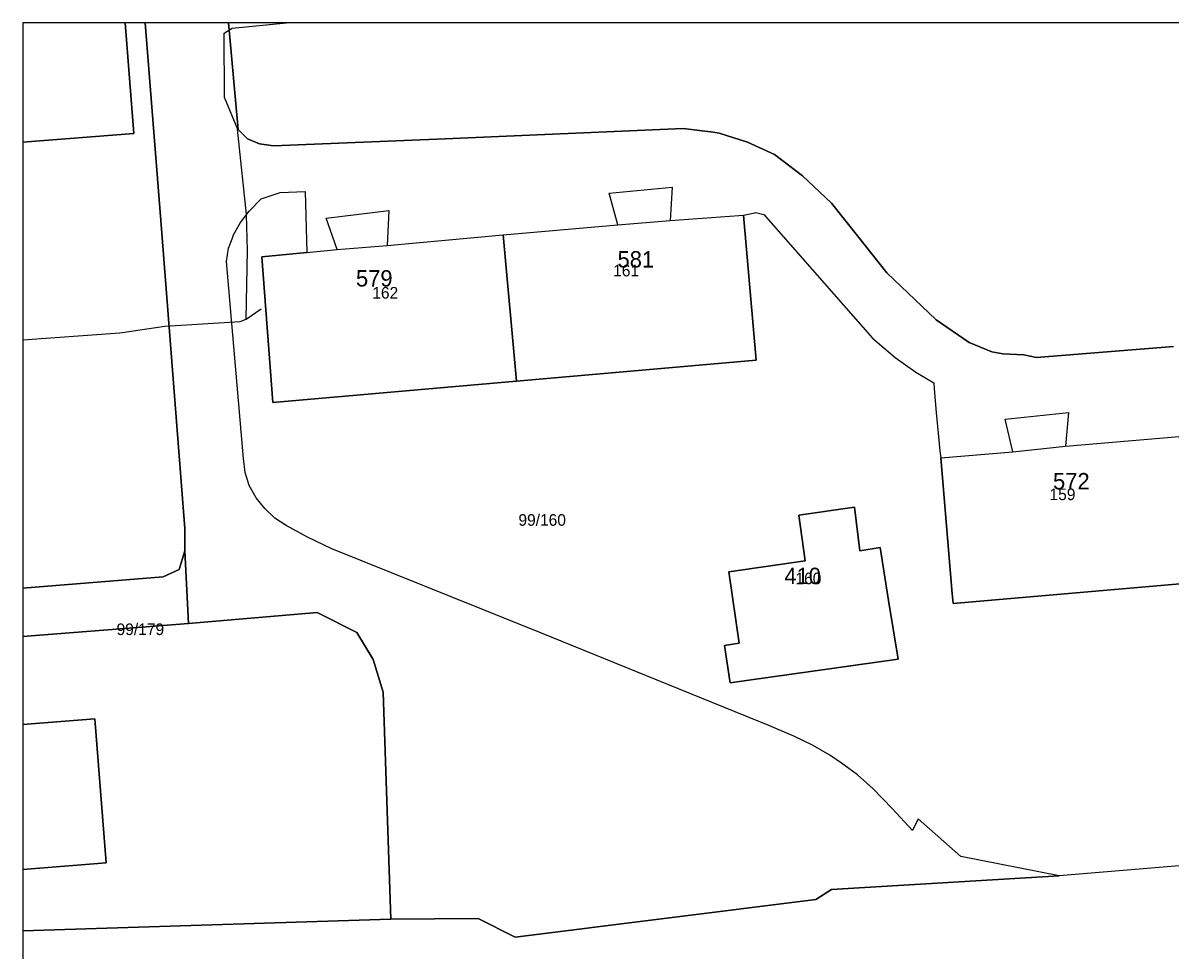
# Model space of a CAD drawing. Extents: x -873642 to -872917, y -1012962 to -1012567.
# Drawn here: x -873642.3 to -873558.3, y -1012635.4 to -1012567.5 of the extents above; entities that cross this region are included whole.
import ezdxf

# ---------------------------------------------------------------- set-up
doc = ezdxf.new("R2010")
doc.units = 0
for name, color, linetype in [('adresni_misto', 7, 'Continuous'), ('cisla_parcelni_kn', 7, 'Continuous'), ('cislo_domovni', 7, 'Continuous'), ('parcely_kn', 7, 'Continuous'), ('stavebni_objekty_bydleni', 7, 'Continuous'), ('TRASY - zamereno', 7, 'Continuous')]:
    doc.layers.add(name, color=color, linetype=linetype)

msp = doc.modelspace()

# ---------------------------------------------------------------- linework, layer by layer
at = {"layer": 'adresni_misto'}
for p, q in [((-873597.18, -1012586.3), (-873597.18, -1012586.3)), ((-873616.32, -1012587.69), (-873616.32, -1012587.69)), ((-873565.31, -1012602.54), (-873565.31, -1012602.54)), ((-873584.97, -1012609.47), (-873584.97, -1012609.47))]:
    msp.add_line(p, q, dxfattribs=at)
at = {"layer": 'parcely_kn'}
for p, q in [((-873633.357, -1012567.5), (-873634.821, -1012567.5)), ((-873633.357, -1012567.5), (-873634.821, -1012567.5)), ((-873627.261, -1012567.5), (-873633.357, -1012567.5)), ((-873627.261, -1012567.5), (-873633.357, -1012567.5)), ((-873506.515, -1012567.5), (-873627.261, -1012567.5)), ((-873506.515, -1012567.5), (-873627.261, -1012567.5)), ((-873642.294, -1012576.233), (-873642.294, -1012608.874)), ((-873642.294, -1012576.233), (-873642.294, -1012608.874)), ((-873642.294, -1012608.874), (-873642.294, -1012612.398)), ((-873642.294, -1012608.874), (-873642.294, -1012612.398)), ((-873642.294, -1012612.398), (-873642.294, -1012618.84)), ((-873642.294, -1012612.398), (-873642.294, -1012618.84)), ((-873642.294, -1012618.84), (-873642.294, -1012629.458)), ((-873642.294, -1012618.84), (-873642.294, -1012629.458)), ((-873642.294, -1012629.458), (-873642.294, -1012633.957)), ((-873642.294, -1012629.458), (-873642.294, -1012633.957)), ((-873642.294, -1012633.957), (-873642.294, -1012646.913))]:
    msp.add_line(p, q, dxfattribs=at)
for points in [[(-873634.821, -1012567.5), (-873642.294, -1012567.5), (-873642.294, -1012576.233)], [(-873642.294, -1012576.233), (-873634.18, -1012575.59), (-873634.821, -1012567.5)], [(-873634.821, -1012567.5), (-873634.18, -1012575.59), (-873642.294, -1012576.233)], [(-873642.294, -1012608.874), (-873632.03, -1012608.04), (-873630.87, -1012607.49), (-873630.45, -1012606.13), (-873630.44, -1012604.49), (-873632.13, -1012582.89), (-873633.357, -1012567.5)], [(-873634.821, -1012567.5), (-873642.294, -1012567.5), (-873642.294, -1012576.233)], [(-873642.294, -1012576.233), (-873634.18, -1012575.59), (-873634.821, -1012567.5)], [(-873634.821, -1012567.5), (-873634.18, -1012575.59), (-873642.294, -1012576.233)], [(-873642.294, -1012608.874), (-873632.03, -1012608.04), (-873630.87, -1012607.49), (-873630.45, -1012606.13), (-873630.44, -1012604.49), (-873632.13, -1012582.89), (-873633.357, -1012567.5)], [(-873633.357, -1012567.5), (-873632.13, -1012582.89), (-873630.44, -1012604.49), (-873630.45, -1012606.13), (-873630.18, -1012611.45), (-873620.75, -1012610.65), (-873617.85, -1012612.12), (-873616.66, -1012614.09), (-873615.92, -1012616.49), (-873615.37, -1012633.09), (-873608.98, -1012633.05), (-873606.27, -1012634.41), (-873584.28, -1012631.65), (-873583.11, -1012630.93), (-873566.46, -1012629.92), (-873573.66, -1012628.51), (-873576.77, -1012625.74), (-873577.19, -1012626.61), (-873578.67, -1012625), (-873580.08, -1012623.56), (-873581.21, -1012622.54), (-873582.39, -1012621.68), (-873583.24, -1012621.1), (-873584.51, -1012620.36), (-873585.87, -1012619.71), (-873587.7, -1012618.91), (-873595.11, -1012615.92), (-873604.35, -1012612.15), (-873619.68, -1012606), (-873621.48, -1012605.14), (-873623.04, -1012604.29), (-873623.86, -1012603.74), (-873624.6, -1012603.03), (-873625.23, -1012602.26), (-873625.74, -1012601.35), (-873626.03, -1012600.4), (-873626.15, -1012599.39), (-873627.4, -1012584.95), (-873627.26, -1012583.98), (-873626.99, -1012583.3), (-873626.88, -1012583.02), (-873626.37, -1012582.1), (-873625.75, -1012581.28), (-873624.85, -1012580.37), (-873623.48, -1012579.91), (-873621.64, -1012579.84), (-873621.52, -1012584.29), (-873619.31, -1012584.07), (-873620.1, -1012581.78), (-873615.52, -1012581.23), (-873615.65, -1012583.79), (-873607.14, -1012583.02), (-873598.75, -1012582.27), (-873599.39, -1012579.96), (-873594.79, -1012579.53), (-873594.92, -1012581.97), (-873589.55, -1012581.56), (-873588.74, -1012581.4), (-873588.65, -1012581.38), (-873588.08, -1012581.53), (-873580.11, -1012590.56), (-873578.47, -1012591.99), (-873576.96, -1012593.07), (-873575.64, -1012593.84), (-873575.6, -1012594.27), (-873575.45, -1012596), (-873575.2, -1012598.82), (-873575.13, -1012599.33), (-873569.85, -1012598.9), (-873570.42, -1012596.51), (-873565.77, -1012596.02), (-873566, -1012598.47), (-873557.68, -1012597.76)], [(-873633.357, -1012567.5), (-873632.13, -1012582.89), (-873630.44, -1012604.49), (-873630.45, -1012606.13), (-873630.18, -1012611.45), (-873620.75, -1012610.65), (-873617.85, -1012612.12), (-873616.66, -1012614.09), (-873615.92, -1012616.49), (-873615.37, -1012633.09), (-873608.98, -1012633.05), (-873606.27, -1012634.41), (-873584.28, -1012631.65), (-873583.11, -1012630.93), (-873566.46, -1012629.92), (-873573.66, -1012628.51), (-873576.77, -1012625.74), (-873577.19, -1012626.61), (-873578.67, -1012625), (-873580.08, -1012623.56), (-873581.21, -1012622.54), (-873582.39, -1012621.68), (-873583.24, -1012621.1), (-873584.51, -1012620.36), (-873585.87, -1012619.71), (-873587.7, -1012618.91), (-873595.11, -1012615.92), (-873604.35, -1012612.15), (-873619.68, -1012606), (-873621.48, -1012605.14), (-873623.04, -1012604.29), (-873623.86, -1012603.74), (-873624.6, -1012603.03), (-873625.23, -1012602.26), (-873625.74, -1012601.35), (-873626.03, -1012600.4), (-873626.15, -1012599.39), (-873627.4, -1012584.95), (-873627.26, -1012583.98), (-873626.99, -1012583.3), (-873626.88, -1012583.02), (-873626.37, -1012582.1), (-873625.75, -1012581.28), (-873624.85, -1012580.37), (-873623.48, -1012579.91), (-873621.64, -1012579.84), (-873621.52, -1012584.29), (-873619.31, -1012584.07), (-873620.1, -1012581.78), (-873615.52, -1012581.23), (-873615.65, -1012583.79), (-873607.14, -1012583.02), (-873598.75, -1012582.27), (-873599.39, -1012579.96), (-873594.79, -1012579.53), (-873594.92, -1012581.97), (-873589.55, -1012581.56), (-873588.74, -1012581.4), (-873588.65, -1012581.38), (-873588.08, -1012581.53), (-873580.11, -1012590.56), (-873578.47, -1012591.99), (-873576.96, -1012593.07), (-873575.64, -1012593.84), (-873575.6, -1012594.27), (-873575.45, -1012596), (-873575.2, -1012598.82), (-873575.13, -1012599.33), (-873569.85, -1012598.9), (-873570.42, -1012596.51), (-873565.77, -1012596.02), (-873566, -1012598.47), (-873557.68, -1012597.76)], [(-873627.261, -1012567.5), (-873626.54, -1012575.29), (-873625.87, -1012575.98), (-873624.99, -1012576.34), (-873623.96, -1012576.49), (-873611.39, -1012575.98), (-873593.98, -1012575.22), (-873591.78, -1012575.5), (-873591.35, -1012575.56), (-873589.27, -1012576.23), (-873587.29, -1012577.14), (-873585.24, -1012578.69), (-873583.13, -1012580.69), (-873581.22, -1012583.07), (-873579.06, -1012585.79), (-873575.47, -1012589.24), (-873573.04, -1012590.88), (-873571.4, -1012591.57), (-873570.58, -1012591.72), (-873569.04, -1012591.8), (-873568.11, -1012591.98), (-873558.1, -1012591.17)], [(-873558.1, -1012591.17), (-873568.11, -1012591.98), (-873569.04, -1012591.8), (-873570.58, -1012591.72), (-873571.4, -1012591.57), (-873573.04, -1012590.88), (-873575.47, -1012589.24), (-873579.06, -1012585.79), (-873581.22, -1012583.07), (-873583.13, -1012580.69), (-873585.24, -1012578.69), (-873587.29, -1012577.14), (-873589.27, -1012576.23), (-873591.35, -1012575.56), (-873591.78, -1012575.5), (-873593.98, -1012575.22), (-873611.39, -1012575.98), (-873623.96, -1012576.49), (-873624.99, -1012576.34), (-873625.87, -1012575.98), (-873626.54, -1012575.29), (-873627.261, -1012567.5)], [(-873627.261, -1012567.5), (-873626.54, -1012575.29), (-873625.87, -1012575.98), (-873624.99, -1012576.34), (-873623.96, -1012576.49), (-873611.39, -1012575.98), (-873593.98, -1012575.22), (-873591.78, -1012575.5), (-873591.35, -1012575.56), (-873589.27, -1012576.23), (-873587.29, -1012577.14), (-873585.24, -1012578.69), (-873583.13, -1012580.69), (-873581.22, -1012583.07), (-873579.06, -1012585.79), (-873575.47, -1012589.24), (-873573.04, -1012590.88), (-873571.4, -1012591.57), (-873570.58, -1012591.72), (-873569.04, -1012591.8), (-873568.11, -1012591.98), (-873558.1, -1012591.17)], [(-873558.1, -1012591.17), (-873568.11, -1012591.98), (-873569.04, -1012591.8), (-873570.58, -1012591.72), (-873571.4, -1012591.57), (-873573.04, -1012590.88), (-873575.47, -1012589.24), (-873579.06, -1012585.79), (-873581.22, -1012583.07), (-873583.13, -1012580.69), (-873585.24, -1012578.69), (-873587.29, -1012577.14), (-873589.27, -1012576.23), (-873591.35, -1012575.56), (-873591.78, -1012575.5), (-873593.98, -1012575.22), (-873611.39, -1012575.98), (-873623.96, -1012576.49), (-873624.99, -1012576.34), (-873625.87, -1012575.98), (-873626.54, -1012575.29), (-873627.261, -1012567.5)], [(-873491.33, -1012623.66), (-873566.46, -1012629.92), (-873573.66, -1012628.51), (-873576.77, -1012625.74), (-873577.19, -1012626.61), (-873578.67, -1012625), (-873580.08, -1012623.56), (-873581.21, -1012622.54), (-873582.39, -1012621.68), (-873583.24, -1012621.1), (-873584.51, -1012620.36), (-873585.87, -1012619.71), (-873587.7, -1012618.91), (-873595.11, -1012615.92), (-873604.35, -1012612.15), (-873619.68, -1012606), (-873621.48, -1012605.14), (-873623.04, -1012604.29), (-873623.86, -1012603.74), (-873624.6, -1012603.03), (-873625.23, -1012602.26), (-873625.74, -1012601.35), (-873626.03, -1012600.4), (-873626.15, -1012599.39), (-873627.4, -1012584.95), (-873627.26, -1012583.98), (-873626.99, -1012583.3), (-873626.88, -1012583.02), (-873626.37, -1012582.1), (-873625.75, -1012581.28), (-873624.85, -1012580.37), (-873623.48, -1012579.91), (-873621.64, -1012579.84), (-873621.52, -1012584.29), (-873624.8, -1012584.62), (-873624.01, -1012595.27), (-873606.18, -1012593.72), (-873588.63, -1012592.19), (-873589.55, -1012581.56), (-873588.74, -1012581.4), (-873588.65, -1012581.38), (-873588.08, -1012581.53), (-873580.11, -1012590.56), (-873578.47, -1012591.99), (-873576.96, -1012593.07), (-873575.64, -1012593.84), (-873575.6, -1012594.27), (-873575.45, -1012596), (-873575.2, -1012598.82), (-873575.13, -1012599.33), (-873574.28, -1012609.27), (-873574.22, -1012610), (-873556.77, -1012608.47)], [(-873491.33, -1012623.66), (-873566.46, -1012629.92), (-873573.66, -1012628.51), (-873576.77, -1012625.74), (-873577.19, -1012626.61), (-873578.67, -1012625), (-873580.08, -1012623.56), (-873581.21, -1012622.54), (-873582.39, -1012621.68), (-873583.24, -1012621.1), (-873584.51, -1012620.36), (-873585.87, -1012619.71), (-873587.7, -1012618.91), (-873595.11, -1012615.92), (-873604.35, -1012612.15), (-873619.68, -1012606), (-873621.48, -1012605.14), (-873623.04, -1012604.29), (-873623.86, -1012603.74), (-873624.6, -1012603.03), (-873625.23, -1012602.26), (-873625.74, -1012601.35), (-873626.03, -1012600.4), (-873626.15, -1012599.39), (-873627.4, -1012584.95), (-873627.26, -1012583.98), (-873626.99, -1012583.3), (-873626.88, -1012583.02), (-873626.37, -1012582.1), (-873625.75, -1012581.28), (-873624.85, -1012580.37), (-873623.48, -1012579.91), (-873621.64, -1012579.84), (-873621.52, -1012584.29), (-873624.8, -1012584.62), (-873624.01, -1012595.27), (-873606.18, -1012593.72), (-873588.63, -1012592.19), (-873589.55, -1012581.56), (-873588.74, -1012581.4), (-873588.65, -1012581.38), (-873588.08, -1012581.53), (-873580.11, -1012590.56), (-873578.47, -1012591.99), (-873576.96, -1012593.07), (-873575.64, -1012593.84), (-873575.6, -1012594.27), (-873575.45, -1012596), (-873575.2, -1012598.82), (-873575.13, -1012599.33), (-873574.28, -1012609.27), (-873574.22, -1012610), (-873556.77, -1012608.47)], [(-873143.44, -1012597.91), (-873216.55, -1012603.73), (-873279.94, -1012608.27), (-873348.3, -1012613.15), (-873406.66, -1012617.85), (-873469.84, -1012622.48), (-873491.33, -1012623.66), (-873566.46, -1012629.92), (-873583.11, -1012630.93), (-873584.28, -1012631.65), (-873606.27, -1012634.41), (-873608.98, -1012633.05), (-873615.37, -1012633.09), (-873642.294, -1012633.957)], [(-873642.294, -1012612.398), (-873630.18, -1012611.45), (-873630.45, -1012606.13), (-873630.87, -1012607.49), (-873632.03, -1012608.04), (-873642.294, -1012608.874)], [(-873642.294, -1012612.398), (-873630.18, -1012611.45), (-873630.45, -1012606.13), (-873630.87, -1012607.49), (-873632.03, -1012608.04), (-873642.294, -1012608.874)], [(-873642.294, -1012633.957), (-873615.37, -1012633.09), (-873615.92, -1012616.49), (-873616.66, -1012614.09), (-873617.85, -1012612.12), (-873620.75, -1012610.65), (-873630.18, -1012611.45), (-873642.294, -1012612.398)], [(-873642.294, -1012633.957), (-873615.37, -1012633.09), (-873615.92, -1012616.49), (-873616.66, -1012614.09), (-873617.85, -1012612.12), (-873620.75, -1012610.65), (-873630.18, -1012611.45), (-873642.294, -1012612.398)], [(-873642.294, -1012629.458), (-873636.2, -1012628.98), (-873637.03, -1012618.43), (-873642.294, -1012618.84)], [(-873642.294, -1012618.84), (-873637.03, -1012618.43), (-873636.2, -1012628.98), (-873642.294, -1012629.458)], [(-873642.294, -1012629.458), (-873636.2, -1012628.98), (-873637.03, -1012618.43), (-873642.294, -1012618.84)], [(-873642.294, -1012618.84), (-873637.03, -1012618.43), (-873636.2, -1012628.98), (-873642.294, -1012629.458)]]:
    msp.add_lwpolyline(points, dxfattribs=at)
for points in [[(-873607.14, -1012583.02), (-873598.75, -1012582.27), (-873599.39, -1012579.96), (-873594.79, -1012579.53), (-873594.92, -1012581.97), (-873589.55, -1012581.56), (-873588.63, -1012592.19), (-873606.18, -1012593.72)], [(-873607.14, -1012583.02), (-873598.75, -1012582.27), (-873599.39, -1012579.96), (-873594.79, -1012579.53), (-873594.92, -1012581.97), (-873589.55, -1012581.56), (-873588.63, -1012592.19), (-873606.18, -1012593.72)], [(-873621.52, -1012584.29), (-873619.31, -1012584.07), (-873620.1, -1012581.78), (-873615.52, -1012581.23), (-873615.65, -1012583.79), (-873607.14, -1012583.02), (-873606.18, -1012593.72), (-873624.01, -1012595.27), (-873624.8, -1012584.62)], [(-873621.52, -1012584.29), (-873619.31, -1012584.07), (-873620.1, -1012581.78), (-873615.52, -1012581.23), (-873615.65, -1012583.79), (-873607.14, -1012583.02), (-873606.18, -1012593.72), (-873624.01, -1012595.27), (-873624.8, -1012584.62)], [(-873556.77, -1012608.47), (-873574.22, -1012610), (-873574.28, -1012609.27), (-873575.13, -1012599.33), (-873569.85, -1012598.9), (-873570.42, -1012596.51), (-873565.77, -1012596.02), (-873566, -1012598.47), (-873557.68, -1012597.76)], [(-873556.77, -1012608.47), (-873574.22, -1012610), (-873574.28, -1012609.27), (-873575.13, -1012599.33), (-873569.85, -1012598.9), (-873570.42, -1012596.51), (-873565.77, -1012596.02), (-873566, -1012598.47), (-873557.68, -1012597.76)], [(-873578.25, -1012614.06), (-873578.94, -1012609.77), (-873579.56, -1012605.88), (-873581.04, -1012606.13), (-873581.44, -1012602.94), (-873585.51, -1012603.53), (-873585.04, -1012606.87), (-873590.64, -1012607.68), (-873589.89, -1012612.9), (-873590.96, -1012613.06), (-873590.56, -1012615.64), (-873590.53, -1012615.8), (-873589.16, -1012615.59)], [(-873585.04, -1012606.87), (-873585.51, -1012603.53), (-873581.44, -1012602.94), (-873581.04, -1012606.13), (-873579.56, -1012605.88), (-873578.94, -1012609.77), (-873578.25, -1012614.06), (-873589.16, -1012615.59), (-873590.53, -1012615.8), (-873590.56, -1012615.64), (-873590.96, -1012613.06), (-873589.89, -1012612.9), (-873590.64, -1012607.68)], [(-873578.25, -1012614.06), (-873578.94, -1012609.77), (-873579.56, -1012605.88), (-873581.04, -1012606.13), (-873581.44, -1012602.94), (-873585.51, -1012603.53), (-873585.04, -1012606.87), (-873590.64, -1012607.68), (-873589.89, -1012612.9), (-873590.96, -1012613.06), (-873590.56, -1012615.64), (-873590.53, -1012615.8), (-873589.16, -1012615.59)], [(-873585.04, -1012606.87), (-873585.51, -1012603.53), (-873581.44, -1012602.94), (-873581.04, -1012606.13), (-873579.56, -1012605.88), (-873578.94, -1012609.77), (-873578.25, -1012614.06), (-873589.16, -1012615.59), (-873590.53, -1012615.8), (-873590.56, -1012615.64), (-873590.96, -1012613.06), (-873589.89, -1012612.9), (-873590.64, -1012607.68)]]:
    msp.add_lwpolyline(points, close=True, dxfattribs=at)
at = {"layer": 'stavebni_objekty_bydleni'}
msp.add_line((-873642.294, -1012618.84), (-873642.294, -1012629.458), dxfattribs=at)
for points in [[(-873634.821, -1012567.5), (-873642.294, -1012567.5), (-873642.294, -1012576.233)], [(-873642.294, -1012576.233), (-873634.18, -1012575.59), (-873634.821, -1012567.5)], [(-873642.294, -1012629.458), (-873636.2, -1012628.98), (-873637.03, -1012618.43), (-873642.294, -1012618.84)]]:
    msp.add_lwpolyline(points, dxfattribs=at)
for points in [[(-873606.18, -1012593.72), (-873607.14, -1012583.02), (-873598.75, -1012582.27), (-873594.92, -1012581.97), (-873589.55, -1012581.56), (-873588.63, -1012592.19)], [(-873606.18, -1012593.72), (-873624.01, -1012595.27), (-873624.8, -1012584.62), (-873621.52, -1012584.29), (-873619.31, -1012584.07), (-873615.65, -1012583.79), (-873607.14, -1012583.02)], [(-873575.13, -1012599.33), (-873569.85, -1012598.9), (-873566, -1012598.47), (-873557.68, -1012597.76), (-873556.77, -1012608.47), (-873574.22, -1012610), (-873574.28, -1012609.27)], [(-873581.04, -1012606.13), (-873579.56, -1012605.88), (-873578.94, -1012609.77), (-873578.25, -1012614.06), (-873589.16, -1012615.59), (-873590.53, -1012615.8), (-873590.56, -1012615.64), (-873590.96, -1012613.06), (-873589.89, -1012612.9), (-873590.64, -1012607.68), (-873585.04, -1012606.87), (-873585.51, -1012603.53), (-873581.44, -1012602.94)]]:
    msp.add_lwpolyline(points, close=True, dxfattribs=at)
at = {"layer": 'TRASY - zamereno'}
for p, q in [((-873626.99, -1012567.89), (-873622.994, -1012567.5)), ((-873627.56, -1012568.25), (-873626.99, -1012567.89)), ((-873627.55, -1012572.98), (-873627.56, -1012568.25)), ((-873627.55, -1012572.98), (-873626.6, -1012575.28)), ((-873625.94, -1012581.52), (-873626.6, -1012575.28)), ((-873625.87, -1012584.16), (-873625.94, -1012581.52)), ((-873625.95, -1012589.17), (-873625.87, -1012584.16)), ((-873625.95, -1012589.17), (-873624.86, -1012588.42)), ((-873626.39, -1012589.35), (-873625.95, -1012589.17)), ((-873635.2, -1012590.18), (-873631.9, -1012589.69)), ((-873631.9, -1012589.69), (-873626.39, -1012589.35)), ((-873642.294, -1012590.696), (-873635.2, -1012590.18))]:
    msp.add_line(p, q, dxfattribs=at)

# ---------------------------------------------------------------- texts
at = {"layer": 'cisla_parcelni_kn'}
for s, p in [('161', (-873599.102, -1012586.05)), ('161', (-873599.102, -1012586.05)), ('162', (-873616.727, -1012587.675)), ('162', (-873616.727, -1012587.675)), ('159', (-873567.165, -1012602.425)), ('159', (-873567.165, -1012602.425)), ('99/160', (-873606.033, -1012604.3)), ('99/160', (-873606.033, -1012604.3)), ('160', (-873585.758, -1012608.581)), ('160', (-873585.758, -1012608.581)), ('99/179', (-873635.44, -1012612.3)), ('99/179', (-873635.44, -1012612.3))]:
    msp.add_text(s, height=0.85, dxfattribs=at).set_placement(p)
at = {"layer": 'cislo_domovni'}
for s, p in [('581', (-873598.78, -1012585.4)), ('579', (-873617.92, -1012586.79)), ('572', (-873566.91, -1012601.64)), ('410', (-873586.57, -1012608.57))]:
    msp.add_text(s, height=1.2, dxfattribs=at).set_placement(p)

doc.saveas('drawing.dxf')
